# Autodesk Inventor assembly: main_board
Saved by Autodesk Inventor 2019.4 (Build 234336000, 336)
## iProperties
Created: 2020-03
Part Number: main_board
Document SubType Name: Assembly
Designer: Administrator
Title: main_board v1
Author: Administrator
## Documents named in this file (2)
- c:\worker\convert-fusion-r02\tmp\job-1\1612\output\files\65dcbb1a-1ec9-4cec-af47-cc4d06111fe3\b8a94291-c63a-408a-9909-7e0b8dcf21ce.zip.iam
- c:\worker\convert-fusion-r02\tmp\job-1\1612\output\files\65dcbb1a-1ec9-4cec-af47-cc4d06111fe3\PCB Component.iam
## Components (1 placed, 1 different names)
1. PCB Component:1 [sub-assembly]
